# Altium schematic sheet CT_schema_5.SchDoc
size 255 x 245 mm
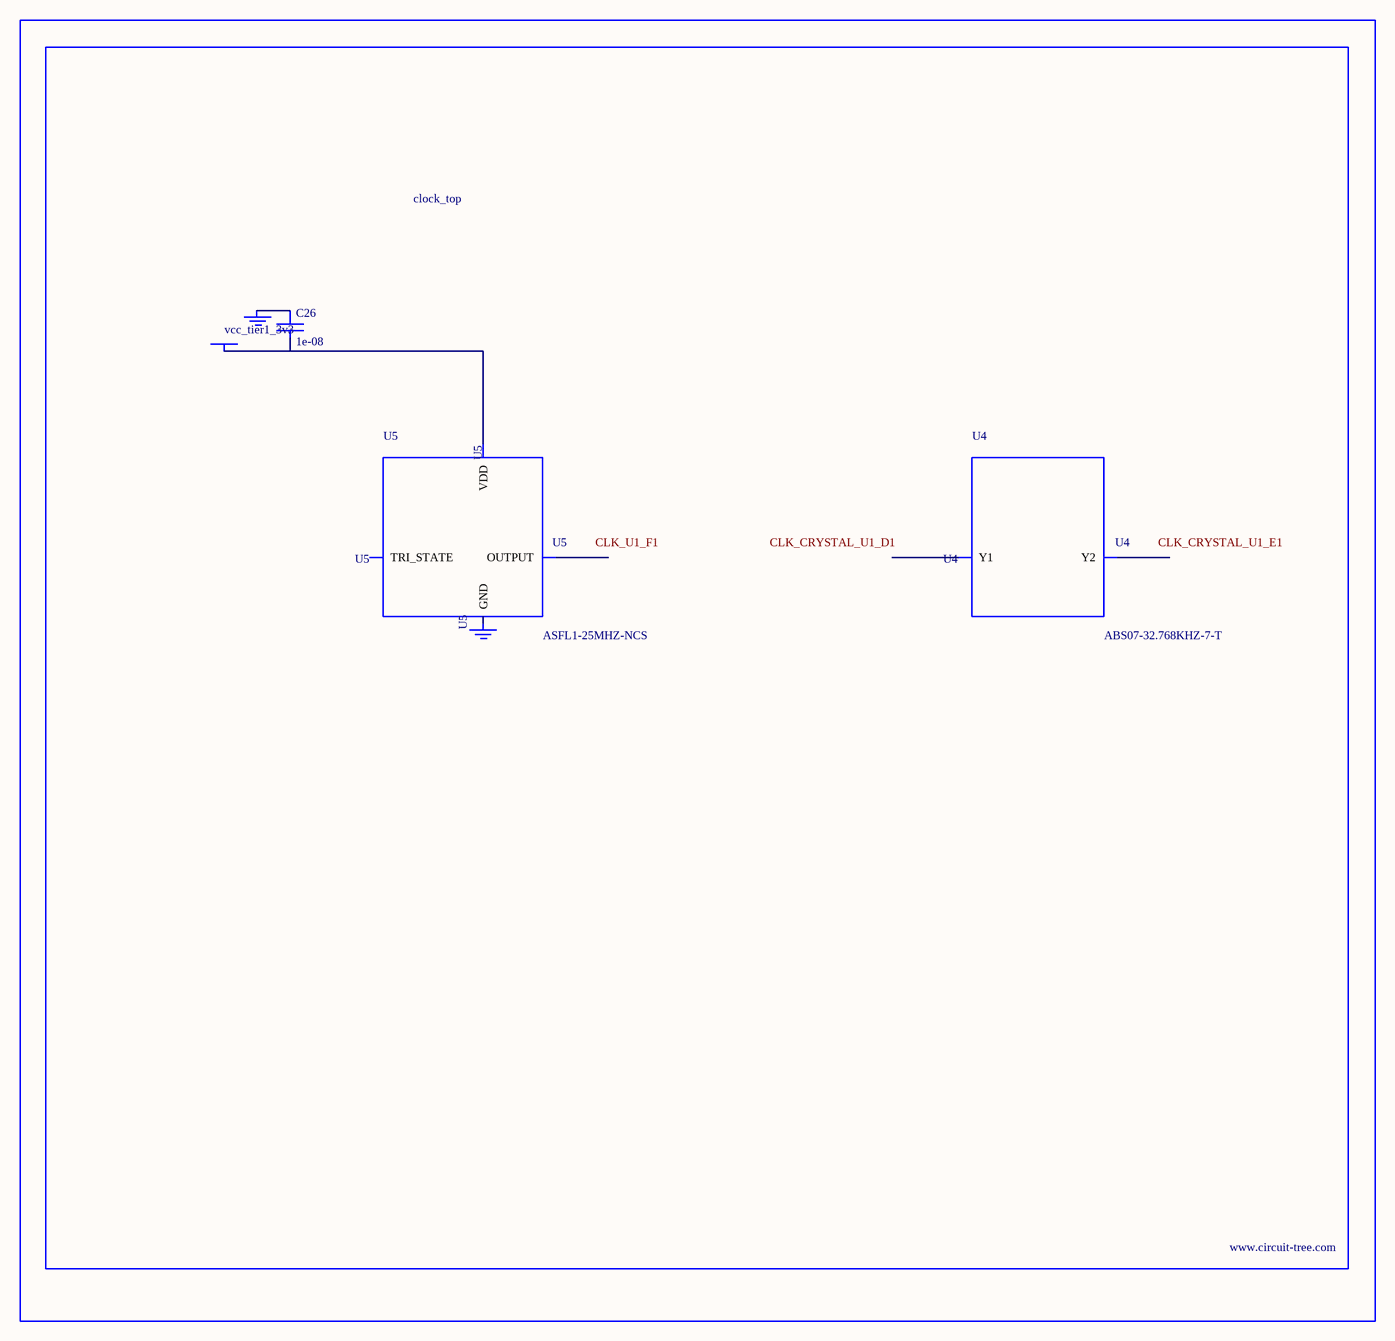
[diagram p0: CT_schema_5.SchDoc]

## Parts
BORDER4  (no value)
C26  1e-08  [C0402]
GND_INSTANCE_4_0  (no value)
GND_INSTANCE_4_1  (no value)
POWER_INSTANCE_4_0  vcc_tier1_3v3
U4  ABS07-32.768KHZ-7-T  [ABS07-32.768KHZ-7-T]
U5  ASFL1-25MHZ-NCS  [ASFL1]

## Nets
NetC26_1: C26.1 GND_INSTANCE_4_0.0(GND)
NetC26_2: C26.2 POWER_INSTANCE_4_0.0(PWR) U5.4(VDD)

Not connected (* = marked no-connect by the designer): GND_INSTANCE_4_1 0(GND); U4 1(Y1) 2(Y2); U5 1(TRI_STATE) 2(GND) 3(OUTPUT)

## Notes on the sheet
- Labels drawn without touching a wire or pin: CLK_CRYSTAL_U1_D1, CLK_CRYSTAL_U1_E1, CLK_U1_F1

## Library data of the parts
BORDER4 = BORDER_PAGE4
C26 = C0402C103K3RAC
GND_INSTANCE_4_0 GND_INSTANCE_4_1 = GND
POWER_INSTANCE_4_0 = PWR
